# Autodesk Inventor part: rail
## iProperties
Shininess: 64.0
Length Units: 11272
Angle Units: 11279
Time Units: 11290
Mass Units: 11286
Length Display Precision: 3
Compacted: True
Part Number: rail
Document SubType Name: Modeling
Created: 2002-11
Designer: E. MOSS
Density: 0.0
Volumn: 0.0
Area: 0.0
PropertySet Name: Model Information
Control State: 0
Master: False
Checked Out: False
Author: E. MOSS
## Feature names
1. Extrusion1
2. Hole1
